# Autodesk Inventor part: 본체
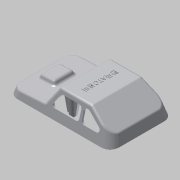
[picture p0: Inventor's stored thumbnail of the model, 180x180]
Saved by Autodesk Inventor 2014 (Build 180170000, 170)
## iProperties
Created: 2015-05
Part Number: 본체
Material: ABS 플라스틱
Document SubType Name: Modeling
Designer: Administrator
Density: 1.06 g/cm^3
Appearance: 매끄러움 - 흰색
Mass: 32.7659 g
Surface Area: 311.132 cm^2
Volume: 30.9112 cm^3
Author: Administrator
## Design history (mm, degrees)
sketch "스케치2"
  geometry: L1 (61, 0)-(-61, 0); L2 (-61, 0)-(-61, 10); L3 (-61, 10)-(-57.782, 12.011); L4 (6.614, 30)-(19.058, 10.086); L5 (19.058, 10.086)-(58.856, 8); L6 (61, 7.888)-(61, 0); L7 (61, 0)-(58.856, 8); L8 (58.856, 8)-(61, 7.888); L9 (-61, 0)-(-57.782, 12.011); L10 (6.614, 30)-(-31, 30); L11 (-31, 30)-(-57.782, 12.011); 2 further points
  constraints: 22 end point, 3 perpendicular, 1 coincident, 1 collinear, 1 horizontal, 1 midpoint, 1 parallel
  dimensions: "d0" = 122 distance of L1.start L1.end; "d1" = 3 deg angle of L1 L5; "d2" = 15 deg angle of L6 L7; "d3" = 8 vertical distance of L1.start L5.end; "d4" = 42 distance of L4.end L6.start; "d5" = 125 deg angle of L5 L4; "d6" = 15 deg angle of L2 L9; "d7" = 30 horizontal distance of L10.end L1.end; "d8" = 20 vertical distance of L10.end L2.end; "d39" = 30 horizontal distance of L2.end L10.end
extrude "돌출1" new body sketch "스케치2" stored distance "d10" = 76; taper "d11" = 0 deg
sketch "스케치3"
  geometry: L1 (-38, 30)-(-38, 10.086) reference; L2 (38, 30)-(-38, 30) reference; L3 (-38, 30)-(-29.962, 30); L4 (-29.962, 30)-(-38, 0); L5 (-38, 0)-(-38, 30); 2 further points
  constraints: 6 end point, 2 collinear, 1 coincident, 1 perpendicular
  dimensions: "d12" = 15 deg angle of L1 L4
extrude "돌출2" cut sketch "스케치3" stored distance "d13" = 76; taper "d14" = 0 deg
fillet "모깎기1" dims "d15" = 12
sketch "스케치4"
  geometry: L1 (-39.853, 59.563)-(-39.853, 11.032) reference; L2 (-31.413, 48.298)-(-11.413, 48.298); L3 (-11.413, 48.298)-(-11.413, 22.298); L4 (-11.413, 22.298)-(-31.413, 22.298); L5 (-31.413, 22.298)-(-31.413, 48.298); L6 (-42.413, 8.889)-(-42.413, 61.706) reference; 3 further points
  constraints: 8 end point, 2 midpoint, 2 parallel, 1 horizontal, 1 horizontal alignment, 1 perpendicular
  dimensions: "d16" = 20 distance of L2.start L2.end; "d17" = 26 distance of L2.end L3.end; "d18" = 11 distance between parallel lines of L6 L5
extrude "돌출3" join sketch "스케치4" distance "d19" = 5; taper "d20" = -20 deg
fillet "모깎기2" dims "d21" = 3
fillet "모깎기3" dims "d22" = 3
feature "쉘1" dims "d23" = 2
sketch "스케치5"
  geometry: L1 (98.679, -73.929)-(0.139, -73.929) reference; L2 (-9.521, -64.27)-(-9.521, -11.73) reference; L3 (0.139, -2.071)-(98.679, -2.071) reference; L4 (108.338, -11.73)-(108.338, -64.27) reference; L5 (98.679, -1.071)-(0.139, -1.071); L6 (-10.521, -11.73)-(-10.521, -64.27); L7 (0.139, -74.929)-(98.679, -74.929); L8 (109.338, -64.27)-(109.338, -11.73); 5 further points; 4 other entities
  constraints: 8 end point, 7 parallel, 16 other
  dimensions: "d24" = 1 distance between parallel lines of L5 L3
extrude "돌출4" join sketch "스케치5" distance "d25" = 1; taper "d26" = 0 deg
node "작업 평면2"
sketch "스케치7"
  geometry: L1 (7.495, 28.59)-(18.23, 11.41) reference; L2 (-30.086, 30)-(4.951, 30) reference; L3 (-46.246, 19.759)-(-31.759, 29.49) reference; L4 (10.347, 14.59)-(4.723, 23.59); L5 (2.179, 25)-(-17.785, 25); L6 (-20.785, 22)-(-20.785, 13); L7 (-17.785, 10)-(7.803, 10); L8 (-23.808, 22)-(-23.808, 13); L9 (-26.808, 10)-(-41.962, 10); L10 (-43.634, 15.49)-(-30.235, 24.49); L11 (-28.563, 25)-(-26.808, 25); A1 r 3 centre (2.179, 22) between (4.723, 23.59) and (2.179, 25); A2 r 3 centre (7.803, 13) between (7.803, 10) and (10.347, 14.59); A3 r 3 centre (-17.785, 13) between (-20.785, 13) and (-17.785, 10); A4 r 3 centre (-17.785, 22) between (-17.785, 25) and (-20.785, 22); A5 r 3 centre (-26.808, 22) between (-23.808, 22) and (-26.808, 25); A6 r 3 centre (-28.563, 22) between (-28.563, 25) and (-30.235, 24.49); A7 r 3 centre (-26.808, 13) between (-26.808, 10) and (-23.808, 13); A8 r 3 centre (-41.962, 13) between (-43.634, 15.49) and (-41.962, 10); 7 further points
  constraints: 16 end point, 16 point on circle, 16 tangent, 12 point on line, 8 centre point, 7 equal radius, 4 parallel, 4 perpendicular
  dimensions: "d41" = 5 distance between parallel lines of L1 L4; "d42" = 5 distance between parallel lines of L2 L5; "d43" = 34 distance of point (-20.785, 10) point (13.215, 10); "d44" = 15 distance of point (-20.785, 25) point (-20.785, 10); "d45" = 15 distance of point (-23.808, 25) point (-23.808, 10); "d46" = 28 distance of point (-23.808, 10) point (-51.808, 10); "d47" = 5 distance between parallel lines of L3 L10; "d48" = 5 distance between parallel lines of L2 L11; "d49" = 3 radius of A1
extrude "돌출5" cut sketch "스케치7" stored distance "d50" = 1; taper "d51" = 0 deg
sketch "스케치8"
  geometry: L1 (65.951, -1.251)-(65.951, -54.068) reference; 2 further points
  constraints: 1 horizontal alignment, 1 other
  dimensions: "d52" = 50 distance from line of L1 point (15.951, -27.66)
feature "엠보싱1" sketch "스케치8" dims "d0" = 122, "d12" = 15 deg, "d53" = 0.5, "d54" = 0
sketch "스케치9"
  geometry: C1 r 3 at (0, -22); C2 r 3 at (0, 22); C3 r 3 at (40, 0); C4 r 3 at (-40, 0); 1 further point
  constraints: 4 centre point, 2 horizontal alignment, 2 vertical alignment
  dimensions: "d55" = 6 diameter of C3; "d56" = 6 diameter of C1; "d57" = 6 diameter of C2; "d58" = 6 diameter of C4; "d59" = 40 distance of C3.centre point (0, 0); "d60" = 40 distance of C4.centre point (0, 0); "d61" = 22 distance of C1.centre point (0, 0); "d62" = 22 distance of point (0, 0) C2.centre
extrude "돌출6" join sketch "스케치9" stored distance "d63" = 1; taper "d64" = 2 deg
node "작업 평면3"
sketch "스케치10"
  geometry: L1 (-45, -1)-(-35, -1); L2 (-35, -1)-(-35, 1); L3 (-35, 1)-(-45, 1); L4 (-45, 1)-(-45, -1); L5 (-45, -1)-(-35, 1); L6 (-35, -1)-(-45, 1); L7 (-5, 21)-(5, 21); L8 (5, 21)-(5, 23); L9 (5, 23)-(-5, 23); L10 (-5, 23)-(-5, 21); L11 (-5, 21)-(5, 23); L12 (5, 21)-(-5, 23); L13 (35, -1)-(45, -1); L14 (45, -1)-(45, 1); L15 (45, 1)-(35, 1); L16 (35, 1)-(35, -1); L17 (35, -1)-(45, 1); L18 (45, -1)-(35, 1); L19 (-5, -23)-(5, -23); L20 (5, -23)-(5, -21); L21 (5, -21)-(-5, -21); L22 (-5, -21)-(-5, -23); L23 (-5, -23)-(5, -21); L24 (5, -23)-(-5, -21); C1 r 3 at (-40, 0) reference; C2 r 3 at (0, -22) reference; C3 r 3 at (0, 22) reference; C4 r 3 at (40, 0) reference; 1 further point
  constraints: 48 end point, 8 midpoint, 8 parallel, 4 horizontal, 4 perpendicular
  dimensions: "d66" = 10 distance of L3.end L2.end; "d67" = 2 distance of L2.end L1.end; "d68" = 10 distance of L9.end L8.end; "d69" = 2 distance of L8.end L7.end; "d70" = 10 distance of L15.end L14.end; "d71" = 2 distance of L14.end L13.end; "d72" = 10 distance of L21.end L20.end; "d73" = 2 distance of L20.end L19.end
  node "투영된 루프1"
  node "투영된 루프2"
  node "투영된 루프3"
  node "투영된 루프4"
extrude "돌출7" join sketch "스케치10" stored distance "d74" = 1; taper "d75" = 2.5 deg
extrude "돌출14" join sketch "스케치10" stored distance "d95" = 1; taper "d96" = 4 deg
sketch "스케치19"
  geometry: L1 (37, 0)-(43, 0) reference; L2 (35, 2)-(34.282, 12.262) reference; L3 (35, 2)-(33.371, 11.24); L4 (33.554, 11.671)-(33.117, 10.641) reference; A1 r 5 centre (28.514, 12.594) between (28.252, 7.601) and (33.117, 10.641) reference; A2 r 1 centre (34.474, 11.281) between (34.527, 12.279) and (33.554, 11.671) reference; 1 further point
  constraints: 2 end point, 1 point on line
  dimensions: "d100" = 80 deg angle of L1 L3
extrude "돌출17" join sketch "스케치19" stored distance "d103" = 1; taper "d104" = 0 deg
sketch "스케치20"
  geometry: L1 (45, 2)-(45.678, 11.695) reference; L2 (47.573, 10.937)-(47.901, 9.866) reference; L3 (34.527, 12.279)-(46.669, 11.643) reference; L4 (45, 2)-(46.959, 11.628); A1 r 5 centre (52.682, 11.328) between (47.901, 9.866) and (52.42, 6.335) reference; A2 r 1 centre (46.617, 10.644) between (47.573, 10.937) and (46.669, 11.643) reference; 1 further point
  constraints: 2 end point, 1 point on line
  dimensions: "d105" = 7.5 deg angle of L1 L4
extrude "돌출18" join sketch "스케치20" stored distance "d106" = 0; taper "d107" = 0 deg
sketch "스케치21"
  geometry: L1 (-35, 2)-(-33.97, 25.596) reference; L2 (-45, 2)-(-45.687, 17.726) reference; L3 (-55.733, 10.978)-(-45.131, 18.099) reference; L4 (4.951, 28)-(-30.086, 28) reference; L5 (-45, 2)-(-47.552, 16.473); 1 further point
  constraints: 2 end point, 1 point on line
  dimensions: "d108" = 7.5 deg angle of L2 L5
extrude "돌출19" join sketch "스케치21" stored distance "d109" = 1; taper "d110" = 0 deg
sketch "스케치22"
  geometry: L1 (-35, 2)-(-33.97, 25.596) reference; L2 (-30.086, 28)-(4.951, 28) reference; L3 (-45.131, 18.099)-(-30.644, 27.83) reference; L4 (-35, 2)-(-30.426, 27.94); A1 r 1 centre (-30.086, 27) between (-30.086, 28) and (-30.644, 27.83) reference; 1 further point
  constraints: 2 end point, 1 point on circle
  dimensions: "d111" = 7.5 deg angle of L1 L4
extrude "돌출20" join sketch "스케치22" stored distance "d112" = 1; taper "d113" = 0 deg
node "작업 평면4"
sketch "스케치23"
  geometry: L1 (5, 2)-(6.094, 27.058) reference; L2 (5.799, 27.53)-(16.534, 10.35) reference; L3 (5, 2)-(8.687, 22.908); 1 further point
  constraints: 2 end point, 1 point on line
  dimensions: "d115" = 7.5 deg angle of L1 L3
extrude "돌출21" join sketch "스케치23" stored distance "d116" = 1; taper "d117" = 0 deg
sketch "스케치24"
  geometry: L1 (-5, 2)-(-6.135, 28) reference; L2 (-30.086, 28)-(4.951, 28) reference; L3 (-5, 2)-(-9.585, 28); 1 further point
  constraints: 2 end point, 1 point on line
  dimensions: "d118" = 7.5 deg angle of L1 L3
extrude "돌출22" join sketch "스케치24" stored distance "d119" = 1; taper "d120" = 0 deg
sketch "스케치25"
  geometry: C1 r 3 at (0, 0) reference; C2 r 3 at (-40, 22) reference; C3 r 3 at (0, 44) reference; C4 r 3 at (40, 22) reference; 5 further points
  constraints: 4 coincident
hole "구멍1" sketch "스케치25" at (0, 44), (40, 22), (0, 0), (-40, 22) diameter "d121" = 3.242; stored, may be unused: countersink angle "d125" = 90 deg, drill point angle "d127" = 118 deg; dims "d122" = 9, "d123" = 4, "d124" = 2, "d126" = 11
node "작업 평면5"
sketch "스케치26"
  geometry: L1 (-26.409, 0)-(26.409, 0) reference; L2 (25, 0)-(17, 0); L3 (14, 0)-(6, 0); A1 r 4 centre (21, 0) between (25, 0) and (17, 0); A2 r 4 centre (10, 0) between (14, 0) and (6, 0); 2 further points
  constraints: 6 horizontal alignment, 4 end point, 4 point on circle, 3 point on line, 2 centre point, 2 collinear, 1 midpoint
  dimensions: "d129" = 4 radius of A1; "d130" = 21 distance of point (0, 0) A1.centre; "d131" = 4 radius of A2; "d132" = 10 distance of point (0, 0) A2.centre
extrude "돌출23" join sketch "스케치26" stored distance "d133" = 1; taper "d134" = 0 deg
chamfer "모따기1" distance "d135" = 1; stored, may be unused: second distance "d136" = 2, angle "d137" = 45 deg
node "솔리드1"
mirror "대칭1"
mirror "대칭2"
mirror "대칭5"
mirror "대칭6"
node "투영된 루프5"
node "투영된 루프6"
node "투영된 루프7"
other parameters: "d40" = -38, "d65" = 2, "d114" = -22, "d128" = -63
